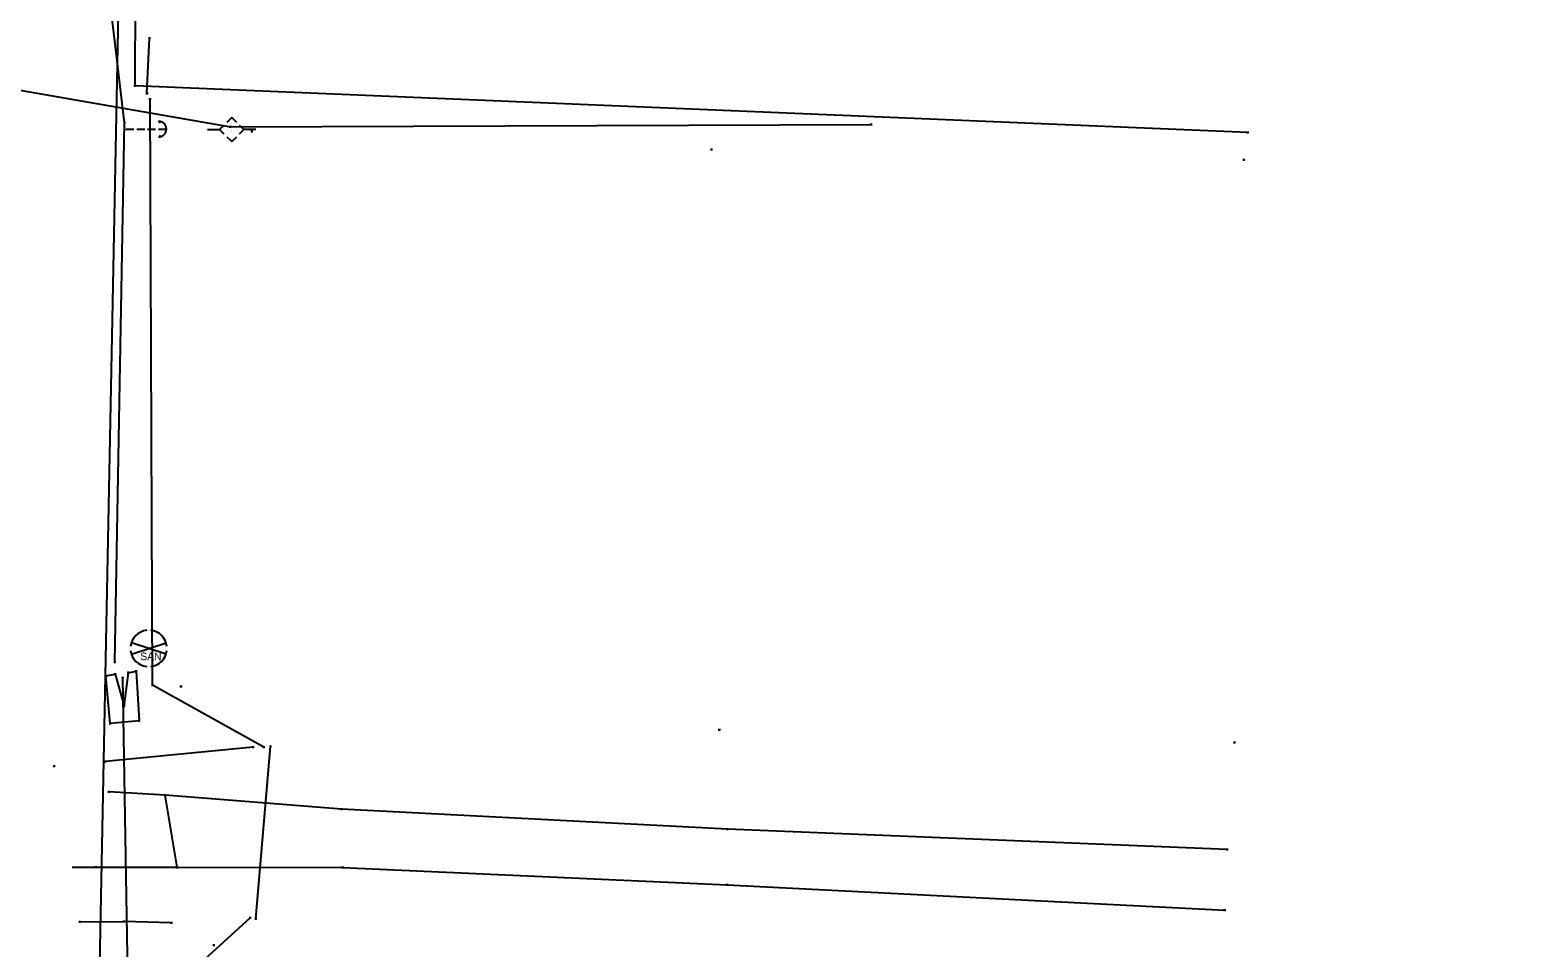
# Model space of a CAD drawing. Extents: x 1954856 to 2011933, y 399149 to 426294.
# Drawn here: x 2003971 to 2004156.8, y 411575.5 to 411688.7 of the extents above; entities that cross this region are included whole.
import ezdxf

# ---------------------------------------------------------------- set-up
doc = ezdxf.new("R2010")
doc.units = 0
for name, color, linetype in [('BankMent_ep', 7, 'Continuous'), ('Driveway_ep', 7, 'Continuous'), ('ElecAer_ep', 7, 'Continuous'), ('EndTreatMES_ep', 7, 'Continuous'), ('Fence_ep', 7, 'Continuous'), ('FlowLineInvert_ep', 7, 'Continuous'), ('Gates_ep', 7, 'Continuous'), ('GovQuarterLine_ep', 7, 'Continuous'), ('GuyWireAnchor_ep', 7, 'Continuous'), ('PipeCulvert_ep', 7, 'Continuous'), ('PointLocator_ep', 7, 'Continuous'), ('PoleElec_ep', 7, 'Continuous'), ('TreeLineWoods_ep', 7, 'Continuous'), ('ValveCvrSewer_ep', 7, 'Continuous')]:
    doc.layers.add(name, color=color, linetype=linetype)

msp = doc.modelspace()

# ---------------------------------------------------------------- linework, layer by layer
at = {"layer": 'BankMent_ep'}
for p, q in [((2003998.46, 411600.29), (2003980.27, 411598.53)), ((2003977.12, 411578.76), (2003982.51, 411578.82)), ((2003988.38, 411578.63), (2003982.51, 411578.82))]:
    msp.add_line(p, q, dxfattribs=at)
msp.add_lwpolyline([(2003981.43, 411610.76), (2003982.6, 411677.27), (2003978.24, 411714.55), (2003977.33, 411779.15), (2003976.33, 411878.57), (2003977.39, 411978.24), (2003978.92, 412079.23), (2003979.2, 412178.28), (2003980.59, 412279.07), (2003979.94, 412378.11), (2003981.17, 412478.71), (2003981.35, 412578.51), (2003981.61, 412678.42), (2003981.57, 412778.96), (2003979.99, 412879.07), (2003982.87, 412922.47), (2003986.24, 412954.3)], dxfattribs=at)
at = {"layer": 'Driveway_ep'}
for p, q in [((2003987.62, 411594.37), (2003980.68, 411594.77)), ((2003989.11, 411585.48), (2003987.62, 411594.37)), ((2003976.15, 411585.52), (2003979.08, 411585.51)), ((2003979.08, 411585.51), (2003989.11, 411585.48))]:
    msp.add_line(p, q, dxfattribs=at)
for points in [[(2004118.52, 411587.67), (2004056.95, 411590.2), (2004009.36, 411592.65), (2003987.62, 411594.37)], [(2003989.11, 411585.48), (2004009.54, 411585.46), (2004056.89, 411583.34), (2004118.23, 411580.18)]]:
    msp.add_lwpolyline(points, dxfattribs=at)
at = {"layer": 'ElecAer_ep'}
msp.add_lwpolyline([(2003912.81, 411691.22), (2003995.68, 411676.8), (2004074.67, 411677.07)], dxfattribs=at)
at = {"layer": 'EndTreatMES_ep'}
msp.add_lwpolyline([(2003980.85, 411603.23), (2003980.33, 411609.09), (2003981.47, 411609.31), (2003982.55, 411605.37), (2003983.09, 411609.48), (2003984.04, 411609.66), (2003984.4, 411603.54)], close=True, dxfattribs=at)
at = {"layer": 'Fence_ep'}
for points in [[(2003985.38, 411680.92), (2003985.68, 411687.73)], [(2003999.78, 411600.3), (2003986.05, 411607.94), (2003985.76, 411680.21)], [(2003985.54, 411492.75), (2003986.52, 411568.68), (2003998.1, 411579.25)]]:
    msp.add_lwpolyline(points, dxfattribs=at)
at = {"layer": 'FlowLineInvert_ep'}
for p, q in [((2003982.47, 411608.75), (2003982.29, 411608.93)), ((2003982.47, 411608.93), (2003982.29, 411608.75)), ((2003982.38, 411608.84), (2003982.38, 411608.84))]:
    msp.add_line(p, q, dxfattribs=at)
at = {"layer": 'Gates_ep'}
msp.add_lwpolyline([(2003998.8, 411579.11), (2004000.62, 411600.37)], dxfattribs=at)
at = {"layer": 'GovQuarterLine_ep'}
msp.add_line((2004007.4, 412995.5), (2003952.93, 410217.34), dxfattribs=at)
at = {"layer": 'GuyWireAnchor_ep'}
for p, q in [((2003982.78, 411676.52), (2003983.78, 411676.52)), ((2003984.12, 411676.52), (2003985.12, 411676.52)), ((2003985.45, 411676.52), (2003986.45, 411676.52)), ((2003986.79, 411676.51), (2003987.79, 411676.51)), ((2003986.81, 411677.49), (2003987, 411677.29)), ((2003987.79, 411676.51), (2003987.79, 411676.51)), ((2003986.83, 411675.54), (2003987.06, 411675.77))]:
    msp.add_line(p, q, dxfattribs=at)
msp.add_arc((2003986.81, 411676.51), 0.973, 271.14, 90.0059, dxfattribs=at)
at = {"layer": 'PipeCulvert_ep'}
msp.add_lwpolyline([(2003982.38, 411608.84), (2003983.04, 411569.73)], dxfattribs=at)
at = {"layer": 'PointLocator_ep'}
for p, q in [((2003985.81, 411687.73), (2003985.56, 411687.73)), ((2003985.68, 411687.6), (2003985.68, 411687.85)), ((2003985.68, 411687.73), (2003985.68, 411687.73)), ((2003984.03, 411681.86), (2003983.78, 411681.86)), ((2003983.91, 411681.73), (2003983.91, 411681.98)), ((2003983.91, 411681.86), (2003983.91, 411681.86)), ((2003985.51, 411680.92), (2003985.26, 411680.92)), ((2003985.38, 411680.79), (2003985.38, 411681.04)), ((2003985.38, 411680.92), (2003985.38, 411680.92)), ((2003985.88, 411680.21), (2003985.63, 411680.21)), ((2003985.76, 411680.09), (2003985.76, 411680.34)), ((2003985.76, 411680.21), (2003985.76, 411680.21)), ((2003982.73, 411677.27), (2003982.48, 411677.27)), ((2003982.6, 411677.15), (2003982.6, 411677.4)), ((2003982.6, 411677.27), (2003982.6, 411677.27)), ((2003995.8, 411676.8), (2003995.55, 411676.8)), ((2003995.68, 411676.67), (2003995.68, 411676.92)), ((2003995.68, 411676.8), (2003995.68, 411676.8)), ((2003998.44, 411676.23), (2003998.19, 411676.23)), ((2003998.31, 411676.1), (2003998.31, 411676.35)), ((2003998.31, 411676.23), (2003998.31, 411676.23)), ((2004074.79, 411677.07), (2004074.54, 411677.07)), ((2004074.67, 411676.94), (2004074.67, 411677.19)), ((2004074.67, 411677.07), (2004074.67, 411677.07)), ((2004121.19, 411676.08), (2004120.94, 411676.08)), ((2004121.06, 411675.96), (2004121.06, 411676.21)), ((2004121.06, 411676.08), (2004121.06, 411676.08)), ((2004055.08, 411674.01), (2004054.83, 411674.01)), ((2004054.96, 411673.88), (2004054.96, 411674.13)), ((2004054.96, 411674.01), (2004054.96, 411674.01)), ((2004120.72, 411672.74), (2004120.47, 411672.74)), ((2004120.59, 411672.61), (2004120.59, 411672.86)), ((2004120.59, 411672.74), (2004120.59, 411672.74)), ((2003980.33, 411608.97), (2003980.33, 411609.22)), ((2003981.55, 411610.76), (2003981.3, 411610.76)), ((2003981.6, 411609.31), (2003981.35, 411609.31)), ((2003981.43, 411610.64), (2003981.43, 411610.89)), ((2003981.43, 411610.76), (2003981.43, 411610.76)), ((2003981.47, 411609.19), (2003981.47, 411609.44)), ((2003981.47, 411609.31), (2003981.47, 411609.31)), ((2003983.21, 411609.48), (2003982.96, 411609.48)), ((2003983.09, 411609.36), (2003983.09, 411609.61)), ((2003983.09, 411609.48), (2003983.09, 411609.48)), ((2003984.16, 411609.66), (2003983.91, 411609.66)), ((2003984.04, 411609.54), (2003984.04, 411609.79)), ((2003984.04, 411609.66), (2003984.04, 411609.66)), ((2003980.46, 411609.09), (2003980.21, 411609.09)), ((2003980.33, 411609.09), (2003980.33, 411609.09)), ((2003986.18, 411607.94), (2003985.93, 411607.94)), ((2003986.05, 411607.82), (2003986.05, 411608.07)), ((2003986.05, 411607.94), (2003986.05, 411607.94)), ((2003989.7, 411607.76), (2003989.45, 411607.76)), ((2003989.58, 411607.64), (2003989.58, 411607.89)), ((2003989.58, 411607.76), (2003989.58, 411607.76)), ((2003982.55, 411605.25), (2003982.55, 411605.5)), ((2003982.68, 411605.37), (2003982.43, 411605.37)), ((2003982.55, 411605.37), (2003982.55, 411605.37)), ((2003984.53, 411603.54), (2003984.28, 411603.54)), ((2003984.4, 411603.42), (2003984.4, 411603.67)), ((2003984.4, 411603.54), (2003984.4, 411603.54)), ((2003980.97, 411603.23), (2003980.72, 411603.23)), ((2003980.85, 411603.1), (2003980.85, 411603.35)), ((2003980.85, 411603.23), (2003980.85, 411603.23)), ((2004056.06, 411602.43), (2004055.81, 411602.43)), ((2004055.93, 411602.31), (2004055.93, 411602.56)), ((2004055.93, 411602.43), (2004055.93, 411602.43)), ((2003998.58, 411600.29), (2003998.33, 411600.29)), ((2003998.46, 411600.16), (2003998.46, 411600.41)), ((2003998.46, 411600.29), (2003998.46, 411600.29)), ((2003999.91, 411600.3), (2003999.66, 411600.3)), ((2003999.78, 411600.18), (2003999.78, 411600.43)), ((2003999.78, 411600.3), (2003999.78, 411600.3)), ((2004000.74, 411600.37), (2004000.49, 411600.37)), ((2004000.62, 411600.25), (2004000.62, 411600.5)), ((2004000.62, 411600.37), (2004000.62, 411600.37)), ((2004119.55, 411600.89), (2004119.3, 411600.89)), ((2004119.43, 411600.76), (2004119.43, 411601.01)), ((2004119.43, 411600.89), (2004119.43, 411600.89)), ((2003973.93, 411597.82), (2003973.93, 411598.07)), ((2003980.39, 411598.53), (2003980.14, 411598.53)), ((2003980.27, 411598.41), (2003980.27, 411598.66)), ((2003980.27, 411598.53), (2003980.27, 411598.53)), ((2003974.05, 411597.94), (2003973.8, 411597.94)), ((2003973.93, 411597.94), (2003973.93, 411597.94)), ((2003980.81, 411594.77), (2003980.56, 411594.77)), ((2003980.68, 411594.65), (2003980.68, 411594.9)), ((2003980.68, 411594.77), (2003980.68, 411594.77)), ((2003987.75, 411594.37), (2003987.5, 411594.37)), ((2003987.62, 411594.25), (2003987.62, 411594.5)), ((2003987.62, 411594.37), (2003987.62, 411594.37)), ((2004009.49, 411592.65), (2004009.24, 411592.65)), ((2004009.36, 411592.52), (2004009.36, 411592.77)), ((2004009.36, 411592.65), (2004009.36, 411592.65)), ((2004057.07, 411590.2), (2004056.82, 411590.2)), ((2004056.95, 411590.08), (2004056.95, 411590.33)), ((2004056.95, 411590.2), (2004056.95, 411590.2)), ((2004118.65, 411587.67), (2004118.4, 411587.67)), ((2004118.52, 411587.54), (2004118.52, 411587.79)), ((2004118.52, 411587.67), (2004118.52, 411587.67)), ((2003979.21, 411585.51), (2003978.96, 411585.51)), ((2003979.08, 411585.39), (2003979.08, 411585.64)), ((2003979.08, 411585.51), (2003979.08, 411585.51)), ((2003989.24, 411585.48), (2003988.99, 411585.48)), ((2003989.11, 411585.35), (2003989.11, 411585.6)), ((2003989.11, 411585.48), (2003989.11, 411585.48)), ((2004009.66, 411585.46), (2004009.41, 411585.46)), ((2004009.54, 411585.34), (2004009.54, 411585.59)), ((2004009.54, 411585.46), (2004009.54, 411585.46)), ((2004057.02, 411583.34), (2004056.77, 411583.34)), ((2004056.89, 411583.21), (2004056.89, 411583.46)), ((2004056.89, 411583.34), (2004056.89, 411583.34)), ((2004118.35, 411580.18), (2004118.1, 411580.18)), ((2004118.23, 411580.06), (2004118.23, 411580.31)), ((2004118.23, 411580.18), (2004118.23, 411580.18)), ((2003977.24, 411578.76), (2003976.99, 411578.76)), ((2003977.12, 411578.64), (2003977.12, 411578.89)), ((2003977.12, 411578.76), (2003977.12, 411578.76)), ((2003982.64, 411578.82), (2003982.39, 411578.82)), ((2003982.51, 411578.69), (2003982.51, 411578.94)), ((2003982.51, 411578.82), (2003982.51, 411578.82)), ((2003988.51, 411578.63), (2003988.26, 411578.63)), ((2003988.38, 411578.5), (2003988.38, 411578.75)), ((2003988.38, 411578.63), (2003988.38, 411578.63)), ((2003998.23, 411579.25), (2003997.98, 411579.25)), ((2003998.1, 411579.12), (2003998.1, 411579.37)), ((2003998.1, 411579.25), (2003998.1, 411579.25)), ((2003998.92, 411579.11), (2003998.67, 411579.11)), ((2003998.8, 411578.99), (2003998.8, 411579.24)), ((2003998.8, 411579.11), (2003998.8, 411579.11)), ((2003993.76, 411575.88), (2003993.51, 411575.88)), ((2003993.63, 411575.75), (2003993.63, 411576)), ((2003993.63, 411575.88), (2003993.63, 411575.88))]:
    msp.add_line(p, q, dxfattribs=at)
at = {"layer": 'PoleElec_ep'}
for p, q in [((2003992.84, 411676.45), (2003994.34, 411676.45)), ((2003994.34, 411676.45), (2003994.91, 411677.02)), ((2003994.91, 411675.89), (2003994.34, 411676.45)), ((2003995.83, 411676.45), (2003995.83, 411676.45)), ((2003998.82, 411676.45), (2003997.32, 411676.45))]:
    msp.add_line(p, q, dxfattribs=at)
for points in [[(2003995.26, 411677.37), (2003995.83, 411677.94), (2003996.4, 411677.37)], [(2003996.75, 411677.02), (2003997.32, 411676.45), (2003996.75, 411675.89)], [(2003996.4, 411675.53), (2003995.83, 411674.97), (2003995.26, 411675.53)]]:
    msp.add_lwpolyline(points, dxfattribs=at)
at = {"layer": 'TreeLineWoods_ep'}
msp.add_lwpolyline([(2004121.06, 411676.08), (2003983.91, 411681.86), (2003984.27, 411779.64), (2003980.55, 411878.04), (2003988.13, 411978.2), (2003984.93, 412079.19), (2003985.61, 412178.24), (2003984.75, 412278.96), (2003987.13, 412377.37), (2003988.48, 412478.5), (2003987.75, 412578.04), (2003987.83, 412678.34), (2003989.03, 412779.03), (2003988.2, 412879.02), (2003989.52, 412960.26), (2004156.83, 412949.91)], dxfattribs=at)
at = {"layer": 'ValveCvrSewer_ep'}
for p, q in [((2003983.46, 411611.75), (2003987.73, 411613.18)), ((2003987.73, 411611.75), (2003983.46, 411613.18)), ((2003985.6, 411612.47), (2003985.6, 411612.47))]:
    msp.add_line(p, q, dxfattribs=at)
for start, end in [(96.3794, 173.6206), (6.3794, 83.6206), (186.3794, 263.6206), (276.3794, 353.6206)]:
    msp.add_arc((2003985.6, 411612.47), 2.25, start, end, dxfattribs=at)

# ---------------------------------------------------------------- texts
msp.add_text('SAN', height=0.95, dxfattribs=at).set_placement((2003984.56, 411611.02))

doc.saveas('drawing.dxf')
